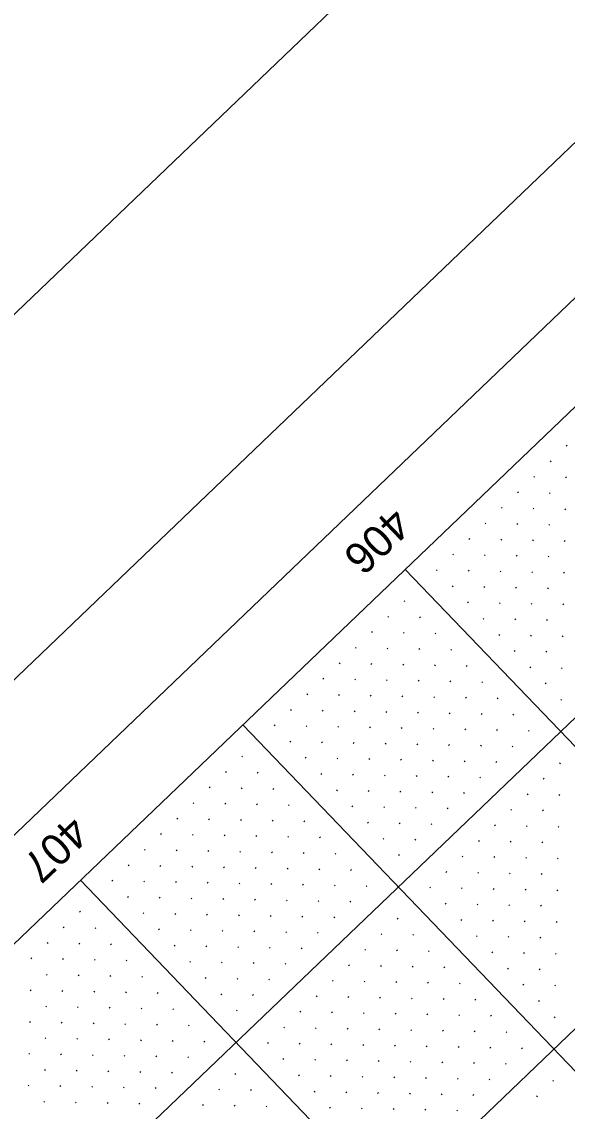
# Model space of a CAD drawing. Extents: x 2148987 to 2151117, y 142806 to 144993.
# Drawn here: x 2150042.8 to 2150164.2, y 144504.6 to 144747.2 of the extents above; entities that cross this region are included whole.
import ezdxf

# ---------------------------------------------------------------- set-up
doc = ezdxf.new("R2010")
doc.units = 0
for name, color, linetype in [('BASELINE', 7, 'Continuous'), ('PR_ABUT_PH3', 7, 'Continuous'), ('PR_PIER_PH3', 7, 'Continuous'), ('PR_Road_Concrete', 7, 'Continuous'), ('SHT_Profile_Grid_Minor', 7, 'Continuous'), ('Wall D Bore Txt', 7, 'Continuous')]:
    doc.layers.add(name, color=color, linetype=linetype)

msp = doc.modelspace()

# ---------------------------------------------------------------- linework, layer by layer
at = {"layer": 'BASELINE'}
msp.add_lwpolyline([(2151029.45, 144024.32), (2149802.07, 142848.08), (2149040.98, 143642.27), (2150268.36, 144818.51)], close=True, dxfattribs=at)
at = {"layer": 'PR_ABUT_PH3'}
msp.add_lwpolyline([(2151117.11, 144051.19), (2149817.52, 142805.76), (2148987.24, 143672.15), (2150286.82, 144917.58)], close=True, dxfattribs=at)
at = {"layer": 'PR_PIER_PH3'}
for p, q in [((2150261.97, 144684.26), (2149124.83, 143594.52)), ((2150296.56, 144648.16), (2149159.43, 143558.42)), ((2150128.1, 144625.23), (2150449.83, 144289.5)), ((2150092, 144590.63), (2150413.73, 144254.91)), ((2150055.9, 144556.04), (2150377.63, 144220.31))]:
    msp.add_line(p, q, dxfattribs=at)
at = {"layer": 'PR_Road_Concrete'}
msp.add_line((2150227.37, 144720.36), (2149279.76, 143812.24), dxfattribs=at)
msp.add_lwpolyline([(2150941.76, 143974.91), (2149804.63, 142885.16), (2149078.13, 143643.25), (2150215.26, 144733)], close=True, dxfattribs=at)
at = {"layer": 'SHT_Profile_Grid_Minor'}
for p, q in [((2150164.14, 144652.84), (2150163.96, 144652.67)), ((2150160.53, 144649.38), (2150160.35, 144649.21)), ((2150156.92, 144645.92), (2150156.74, 144645.75)), ((2150163.99, 144645.77), (2150163.81, 144645.6)), ((2150153.31, 144642.46), (2150153.13, 144642.29)), ((2150160.38, 144642.31), (2150160.2, 144642.14)), ((2150149.7, 144639), (2150149.52, 144638.83)), ((2150156.77, 144638.85), (2150156.59, 144638.68)), ((2150163.84, 144638.7), (2150163.66, 144638.53)), ((2150146.09, 144635.54), (2150145.91, 144635.37)), ((2150153.16, 144635.39), (2150152.98, 144635.22)), ((2150160.23, 144635.24), (2150160.05, 144635.07)), ((2150142.48, 144632.08), (2150142.3, 144631.91)), ((2150149.55, 144631.93), (2150149.37, 144631.76)), ((2150156.62, 144631.78), (2150156.44, 144631.61)), ((2150163.69, 144631.63), (2150163.51, 144631.46)), ((2150138.87, 144628.62), (2150138.69, 144628.45)), ((2150145.94, 144628.47), (2150145.76, 144628.3)), ((2150153.01, 144628.32), (2150152.83, 144628.15)), ((2150160.08, 144628.17), (2150159.9, 144628)), ((2150135.26, 144625.16), (2150135.08, 144624.99)), ((2150142.33, 144625.01), (2150142.15, 144624.84)), ((2150149.4, 144624.86), (2150149.22, 144624.69)), ((2150156.47, 144624.71), (2150156.29, 144624.54)), ((2150163.54, 144624.56), (2150163.36, 144624.39)), ((2150138.72, 144621.55), (2150138.54, 144621.38)), ((2150145.79, 144621.4), (2150145.61, 144621.23)), ((2150152.86, 144621.25), (2150152.68, 144621.08)), ((2150159.93, 144621.1), (2150159.75, 144620.93)), ((2150128.04, 144618.24), (2150127.86, 144618.07)), ((2150142.18, 144617.94), (2150142, 144617.77)), ((2150149.25, 144617.79), (2150149.07, 144617.62)), ((2150156.32, 144617.64), (2150156.14, 144617.47)), ((2150163.39, 144617.49), (2150163.2, 144617.32)), ((2150124.43, 144614.78), (2150124.25, 144614.61)), ((2150131.5, 144614.63), (2150131.32, 144614.46)), ((2150145.64, 144614.33), (2150145.46, 144614.16)), ((2150152.71, 144614.18), (2150152.53, 144614.01)), ((2150159.78, 144614.03), (2150159.59, 144613.86)), ((2150120.82, 144611.33), (2150120.64, 144611.15)), ((2150127.89, 144611.17), (2150127.71, 144611)), ((2150134.96, 144611.02), (2150134.78, 144610.85)), ((2150149.1, 144610.72), (2150148.92, 144610.55)), ((2150156.17, 144610.57), (2150155.99, 144610.4)), ((2150163.23, 144610.42), (2150163.05, 144610.25)), ((2150117.21, 144607.87), (2150117.03, 144607.69)), ((2150124.28, 144607.72), (2150124.1, 144607.54)), ((2150131.35, 144607.56), (2150131.17, 144607.39)), ((2150138.42, 144607.41), (2150138.24, 144607.24)), ((2150152.56, 144607.11), (2150152.38, 144606.94)), ((2150159.63, 144606.96), (2150159.44, 144606.79)), ((2150113.6, 144604.41), (2150113.42, 144604.23)), ((2150120.67, 144604.26), (2150120.49, 144604.08)), ((2150127.74, 144604.11), (2150127.56, 144603.93)), ((2150134.81, 144603.95), (2150134.63, 144603.78)), ((2150141.88, 144603.8), (2150141.7, 144603.63)), ((2150156.02, 144603.5), (2150155.83, 144603.33)), ((2150163.08, 144603.35), (2150162.9, 144603.18)), ((2150109.99, 144600.95), (2150109.81, 144600.77)), ((2150117.06, 144600.8), (2150116.88, 144600.62)), ((2150124.13, 144600.65), (2150123.95, 144600.47)), ((2150131.2, 144600.5), (2150131.02, 144600.32)), ((2150138.27, 144600.34), (2150138.09, 144600.17)), ((2150145.34, 144600.19), (2150145.16, 144600.02)), ((2150159.47, 144599.89), (2150159.29, 144599.72)), ((2150106.38, 144597.49), (2150106.2, 144597.31)), ((2150113.45, 144597.34), (2150113.27, 144597.16)), ((2150120.52, 144597.19), (2150120.34, 144597.01)), ((2150127.59, 144597.04), (2150127.41, 144596.86)), ((2150134.66, 144596.89), (2150134.48, 144596.71)), ((2150141.73, 144596.73), (2150141.55, 144596.56)), ((2150148.8, 144596.58), (2150148.61, 144596.41)), ((2150162.93, 144596.28), (2150162.75, 144596.11)), ((2150102.77, 144594.03), (2150102.59, 144593.85)), ((2150109.84, 144593.88), (2150109.66, 144593.7)), ((2150116.91, 144593.73), (2150116.73, 144593.55)), ((2150123.98, 144593.58), (2150123.8, 144593.4)), ((2150131.05, 144593.43), (2150130.87, 144593.25)), ((2150138.12, 144593.28), (2150137.94, 144593.1)), ((2150145.19, 144593.12), (2150145, 144592.95)), ((2150152.25, 144592.97), (2150152.07, 144592.8)), ((2150099.16, 144590.57), (2150098.98, 144590.39)), ((2150106.23, 144590.42), (2150106.05, 144590.24)), ((2150113.3, 144590.27), (2150113.12, 144590.09)), ((2150120.37, 144590.12), (2150120.19, 144589.94)), ((2150127.44, 144589.97), (2150127.26, 144589.79)), ((2150134.51, 144589.82), (2150134.33, 144589.64)), ((2150141.58, 144589.67), (2150141.39, 144589.49)), ((2150148.64, 144589.51), (2150148.46, 144589.34)), ((2150155.71, 144589.36), (2150155.53, 144589.19)), ((2150102.62, 144586.96), (2150102.44, 144586.79)), ((2150109.69, 144586.81), (2150109.51, 144586.63)), ((2150116.76, 144586.66), (2150116.58, 144586.48)), ((2150123.83, 144586.51), (2150123.65, 144586.33)), ((2150130.9, 144586.36), (2150130.72, 144586.18)), ((2150137.97, 144586.21), (2150137.78, 144586.03)), ((2150145.03, 144586.06), (2150144.85, 144585.88)), ((2150152.1, 144585.9), (2150151.92, 144585.73)), ((2150091.94, 144583.65), (2150091.76, 144583.48)), ((2150106.08, 144583.35), (2150105.9, 144583.18)), ((2150113.15, 144583.2), (2150112.97, 144583.02)), ((2150120.22, 144583.05), (2150120.04, 144582.87)), ((2150127.29, 144582.9), (2150127.11, 144582.72)), ((2150134.36, 144582.75), (2150134.17, 144582.57)), ((2150141.42, 144582.6), (2150141.24, 144582.42)), ((2150148.49, 144582.45), (2150148.31, 144582.27)), ((2150088.33, 144580.19), (2150088.15, 144580.02)), ((2150095.4, 144580.04), (2150095.22, 144579.87)), ((2150162.63, 144582.14), (2150162.45, 144581.97)), ((2150109.54, 144579.74), (2150109.36, 144579.57)), ((2150116.61, 144579.59), (2150116.43, 144579.41)), ((2150123.68, 144579.44), (2150123.5, 144579.26)), ((2150130.75, 144579.29), (2150130.56, 144579.11)), ((2150137.81, 144579.14), (2150137.63, 144578.96)), ((2150144.88, 144578.99), (2150144.7, 144578.81)), ((2150159.02, 144578.69), (2150158.84, 144578.51)), ((2150084.72, 144576.73), (2150084.54, 144576.56)), ((2150091.79, 144576.58), (2150091.61, 144576.41)), ((2150098.86, 144576.43), (2150098.68, 144576.26)), ((2150113, 144576.13), (2150112.82, 144575.96)), ((2150120.07, 144575.98), (2150119.89, 144575.8)), ((2150127.14, 144575.83), (2150126.95, 144575.65)), ((2150134.2, 144575.68), (2150134.02, 144575.5)), ((2150141.27, 144575.53), (2150141.09, 144575.35)), ((2150155.41, 144575.23), (2150155.23, 144575.05)), ((2150081.11, 144573.27), (2150080.93, 144573.1)), ((2150088.18, 144573.12), (2150088, 144572.95)), ((2150095.25, 144572.97), (2150095.07, 144572.8)), ((2150102.32, 144572.82), (2150102.14, 144572.65)), ((2150162.48, 144575.08), (2150162.3, 144574.9)), ((2150116.46, 144572.52), (2150116.28, 144572.35)), ((2150123.53, 144572.37), (2150123.35, 144572.19)), ((2150130.59, 144572.22), (2150130.41, 144572.04)), ((2150137.66, 144572.07), (2150137.48, 144571.89)), ((2150151.8, 144571.77), (2150151.62, 144571.59)), ((2150158.87, 144571.62), (2150158.69, 144571.44)), ((2150077.5, 144569.81), (2150077.32, 144569.64)), ((2150084.57, 144569.66), (2150084.39, 144569.49)), ((2150091.64, 144569.51), (2150091.46, 144569.34)), ((2150098.71, 144569.36), (2150098.53, 144569.19)), ((2150105.78, 144569.21), (2150105.6, 144569.04)), ((2150119.92, 144568.91), (2150119.74, 144568.74)), ((2150126.99, 144568.76), (2150126.8, 144568.58)), ((2150134.05, 144568.61), (2150133.87, 144568.43)), ((2150148.19, 144568.31), (2150148.01, 144568.13)), ((2150155.26, 144568.16), (2150155.08, 144567.98)), ((2150162.33, 144568.01), (2150162.15, 144567.83)), ((2150073.89, 144566.35), (2150073.71, 144566.18)), ((2150080.96, 144566.2), (2150080.78, 144566.03)), ((2150088.03, 144566.05), (2150087.85, 144565.88)), ((2150095.1, 144565.9), (2150094.92, 144565.73)), ((2150102.17, 144565.75), (2150101.99, 144565.58)), ((2150109.24, 144565.6), (2150109.06, 144565.43)), ((2150123.38, 144565.3), (2150123.19, 144565.13)), ((2150130.44, 144565.15), (2150130.26, 144564.97)), ((2150144.58, 144564.85), (2150144.4, 144564.67)), ((2150151.65, 144564.7), (2150151.47, 144564.52)), ((2150158.72, 144564.55), (2150158.54, 144564.37)), ((2150070.28, 144562.89), (2150070.1, 144562.72)), ((2150077.35, 144562.74), (2150077.17, 144562.57)), ((2150084.42, 144562.59), (2150084.24, 144562.42)), ((2150091.49, 144562.44), (2150091.31, 144562.27)), ((2150098.56, 144562.29), (2150098.38, 144562.12)), ((2150105.63, 144562.14), (2150105.45, 144561.97)), ((2150112.7, 144561.99), (2150112.52, 144561.82)), ((2150126.83, 144561.69), (2150126.65, 144561.52)), ((2150140.97, 144561.39), (2150140.79, 144561.21)), ((2150148.04, 144561.24), (2150147.86, 144561.06)), ((2150155.11, 144561.09), (2150154.93, 144560.91)), ((2150162.18, 144560.94), (2150162, 144560.76)), ((2150066.67, 144559.43), (2150066.49, 144559.26)), ((2150073.74, 144559.28), (2150073.56, 144559.11)), ((2150080.81, 144559.13), (2150080.63, 144558.96)), ((2150087.88, 144558.98), (2150087.7, 144558.81)), ((2150094.95, 144558.83), (2150094.77, 144558.66)), ((2150102.02, 144558.68), (2150101.84, 144558.51)), ((2150109.09, 144558.53), (2150108.91, 144558.36)), ((2150116.16, 144558.38), (2150115.97, 144558.21)), ((2150063.06, 144555.97), (2150062.88, 144555.8)), ((2150070.13, 144555.82), (2150069.95, 144555.65)), ((2150137.36, 144557.93), (2150137.18, 144557.75)), ((2150144.43, 144557.78), (2150144.25, 144557.6)), ((2150151.5, 144557.63), (2150151.32, 144557.45)), ((2150158.57, 144557.48), (2150158.39, 144557.3)), ((2150077.2, 144555.67), (2150077.02, 144555.5)), ((2150084.27, 144555.52), (2150084.09, 144555.35)), ((2150091.34, 144555.37), (2150091.16, 144555.2)), ((2150098.41, 144555.22), (2150098.23, 144555.05)), ((2150105.48, 144555.07), (2150105.3, 144554.9)), ((2150112.55, 144554.92), (2150112.36, 144554.75)), ((2150119.61, 144554.77), (2150119.43, 144554.6)), ((2150133.75, 144554.47), (2150133.57, 144554.3)), ((2150140.82, 144554.32), (2150140.64, 144554.15)), ((2150147.89, 144554.17), (2150147.71, 144553.99)), ((2150154.96, 144554.02), (2150154.78, 144553.84)), ((2150162.03, 144553.87), (2150161.85, 144553.69)), ((2150066.52, 144552.36), (2150066.34, 144552.19)), ((2150073.59, 144552.21), (2150073.41, 144552.04)), ((2150080.66, 144552.06), (2150080.48, 144551.89)), ((2150087.73, 144551.91), (2150087.55, 144551.74)), ((2150094.8, 144551.76), (2150094.62, 144551.59)), ((2150101.87, 144551.61), (2150101.69, 144551.44)), ((2150108.94, 144551.46), (2150108.75, 144551.29)), ((2150116, 144551.31), (2150115.82, 144551.14)), ((2150137.21, 144550.86), (2150137.03, 144550.69)), ((2150055.84, 144549.05), (2150055.66, 144548.88)), ((2150069.98, 144548.75), (2150069.8, 144548.58)), ((2150077.05, 144548.6), (2150076.87, 144548.43)), ((2150084.12, 144548.45), (2150083.94, 144548.28)), ((2150144.28, 144550.71), (2150144.1, 144550.54)), ((2150151.35, 144550.56), (2150151.17, 144550.38)), ((2150158.42, 144550.41), (2150158.24, 144550.23)), ((2150091.19, 144548.3), (2150091.01, 144548.13)), ((2150098.26, 144548.15), (2150098.08, 144547.98)), ((2150105.33, 144548), (2150105.14, 144547.83)), ((2150112.39, 144547.85), (2150112.21, 144547.68)), ((2150126.53, 144547.55), (2150126.35, 144547.38)), ((2150140.67, 144547.25), (2150140.49, 144547.08)), ((2150147.74, 144547.1), (2150147.56, 144546.93)), ((2150154.81, 144546.95), (2150154.63, 144546.77)), ((2150161.88, 144546.8), (2150161.7, 144546.62)), ((2150052.23, 144545.59), (2150052.05, 144545.42)), ((2150059.3, 144545.44), (2150059.12, 144545.27)), ((2150073.44, 144545.14), (2150073.26, 144544.97)), ((2150080.51, 144544.99), (2150080.33, 144544.82)), ((2150087.58, 144544.84), (2150087.4, 144544.67)), ((2150094.65, 144544.69), (2150094.47, 144544.52)), ((2150101.72, 144544.54), (2150101.53, 144544.37)), ((2150108.78, 144544.39), (2150108.6, 144544.22)), ((2150122.92, 144544.09), (2150122.74, 144543.92)), ((2150129.99, 144543.94), (2150129.81, 144543.77)), ((2150144.13, 144543.64), (2150143.95, 144543.47)), ((2150048.62, 144542.13), (2150048.44, 144541.96)), ((2150055.69, 144541.98), (2150055.51, 144541.81)), ((2150062.76, 144541.83), (2150062.58, 144541.66)), ((2150076.9, 144541.53), (2150076.72, 144541.36)), ((2150083.97, 144541.38), (2150083.79, 144541.21)), ((2150091.04, 144541.23), (2150090.86, 144541.06)), ((2150151.2, 144543.49), (2150151.02, 144543.32)), ((2150158.27, 144543.34), (2150158.09, 144543.16)), ((2150098.11, 144541.08), (2150097.92, 144540.91)), ((2150105.17, 144540.93), (2150104.99, 144540.76)), ((2150119.31, 144540.63), (2150119.13, 144540.46)), ((2150126.38, 144540.48), (2150126.2, 144540.31)), ((2150133.45, 144540.33), (2150133.27, 144540.16)), ((2150147.59, 144540.03), (2150147.41, 144539.86)), ((2150154.66, 144539.88), (2150154.48, 144539.71)), ((2150161.73, 144539.73), (2150161.55, 144539.55)), ((2150045.01, 144538.68), (2150044.83, 144538.5)), ((2150052.08, 144538.52), (2150051.9, 144538.35)), ((2150059.15, 144538.37), (2150058.97, 144538.2)), ((2150066.22, 144538.22), (2150066.04, 144538.05)), ((2150080.36, 144537.92), (2150080.18, 144537.75)), ((2150087.43, 144537.77), (2150087.25, 144537.6)), ((2150094.5, 144537.62), (2150094.31, 144537.45)), ((2150101.56, 144537.47), (2150101.38, 144537.3)), ((2150115.7, 144537.17), (2150115.52, 144537)), ((2150122.77, 144537.02), (2150122.59, 144536.85)), ((2150129.84, 144536.87), (2150129.66, 144536.7)), ((2150136.91, 144536.72), (2150136.73, 144536.55)), ((2150151.05, 144536.42), (2150150.87, 144536.25)), ((2150048.47, 144535.07), (2150048.29, 144534.89)), ((2150055.54, 144534.91), (2150055.36, 144534.74)), ((2150062.61, 144534.76), (2150062.43, 144534.59)), ((2150069.68, 144534.61), (2150069.5, 144534.44)), ((2150083.82, 144534.31), (2150083.64, 144534.14)), ((2150090.89, 144534.16), (2150090.7, 144533.99)), ((2150097.95, 144534.01), (2150097.77, 144533.84)), ((2150158.12, 144536.27), (2150157.94, 144536.1)), ((2150044.86, 144531.61), (2150044.68, 144531.43)), ((2150051.93, 144531.46), (2150051.75, 144531.28)), ((2150112.09, 144533.71), (2150111.91, 144533.54)), ((2150119.16, 144533.56), (2150118.98, 144533.39)), ((2150126.23, 144533.41), (2150126.05, 144533.24)), ((2150133.3, 144533.26), (2150133.12, 144533.09)), ((2150140.37, 144533.11), (2150140.19, 144532.94)), ((2150154.51, 144532.81), (2150154.33, 144532.64)), ((2150161.58, 144532.66), (2150161.4, 144532.49)), ((2150059, 144531.3), (2150058.82, 144531.13)), ((2150066.07, 144531.15), (2150065.89, 144530.98)), ((2150073.14, 144531), (2150072.96, 144530.83)), ((2150087.28, 144530.7), (2150087.1, 144530.53)), ((2150094.35, 144530.55), (2150094.16, 144530.38)), ((2150108.48, 144530.25), (2150108.3, 144530.08)), ((2150115.55, 144530.1), (2150115.37, 144529.93)), ((2150122.62, 144529.95), (2150122.44, 144529.78)), ((2150129.69, 144529.8), (2150129.51, 144529.63)), ((2150136.76, 144529.65), (2150136.58, 144529.48)), ((2150143.83, 144529.5), (2150143.65, 144529.33)), ((2150157.97, 144529.2), (2150157.79, 144529.03)), ((2150048.32, 144528), (2150048.14, 144527.82)), ((2150055.39, 144527.85), (2150055.21, 144527.67)), ((2150062.46, 144527.69), (2150062.28, 144527.52)), ((2150069.53, 144527.54), (2150069.35, 144527.37)), ((2150076.6, 144527.39), (2150076.42, 144527.22)), ((2150090.74, 144527.09), (2150090.55, 144526.92)), ((2150104.87, 144526.79), (2150104.69, 144526.62)), ((2150111.94, 144526.64), (2150111.76, 144526.47)), ((2150044.71, 144524.54), (2150044.53, 144524.36)), ((2150051.78, 144524.39), (2150051.6, 144524.21)), ((2150058.85, 144524.24), (2150058.67, 144524.06)), ((2150119.01, 144526.49), (2150118.83, 144526.32)), ((2150126.08, 144526.34), (2150125.9, 144526.17)), ((2150133.15, 144526.19), (2150132.97, 144526.02)), ((2150140.22, 144526.04), (2150140.04, 144525.87)), ((2150147.29, 144525.89), (2150147.11, 144525.72)), ((2150161.43, 144525.59), (2150161.25, 144525.42)), ((2150065.92, 144524.08), (2150065.74, 144523.91)), ((2150072.99, 144523.93), (2150072.81, 144523.76)), ((2150080.06, 144523.78), (2150079.88, 144523.61)), ((2150101.26, 144523.33), (2150101.08, 144523.16)), ((2150108.33, 144523.18), (2150108.15, 144523.01)), ((2150115.4, 144523.03), (2150115.22, 144522.86)), ((2150122.47, 144522.88), (2150122.29, 144522.71)), ((2150129.54, 144522.73), (2150129.36, 144522.56)), ((2150136.61, 144522.58), (2150136.43, 144522.41)), ((2150143.68, 144522.43), (2150143.5, 144522.26)), ((2150150.75, 144522.28), (2150150.57, 144522.11)), ((2150048.17, 144520.93), (2150047.99, 144520.75)), ((2150055.24, 144520.78), (2150055.06, 144520.6)), ((2150062.31, 144520.63), (2150062.13, 144520.45)), ((2150069.38, 144520.48), (2150069.2, 144520.3)), ((2150076.45, 144520.32), (2150076.27, 144520.15)), ((2150083.52, 144520.17), (2150083.33, 144520)), ((2150097.65, 144519.87), (2150097.47, 144519.7)), ((2150104.72, 144519.72), (2150104.54, 144519.55)), ((2150111.79, 144519.57), (2150111.61, 144519.4)), ((2150118.86, 144519.42), (2150118.68, 144519.25)), ((2150044.56, 144517.47), (2150044.38, 144517.29)), ((2150051.63, 144517.32), (2150051.45, 144517.14)), ((2150058.7, 144517.17), (2150058.52, 144516.99)), ((2150065.77, 144517.02), (2150065.59, 144516.84)), ((2150125.93, 144519.27), (2150125.75, 144519.1)), ((2150133, 144519.12), (2150132.82, 144518.95)), ((2150140.07, 144518.97), (2150139.89, 144518.8)), ((2150147.14, 144518.82), (2150146.96, 144518.65)), ((2150154.21, 144518.67), (2150154.03, 144518.5)), ((2150072.84, 144516.87), (2150072.66, 144516.69)), ((2150079.91, 144516.71), (2150079.72, 144516.54)), ((2150101.11, 144516.26), (2150100.93, 144516.09)), ((2150108.18, 144516.11), (2150108, 144515.94)), ((2150115.25, 144515.96), (2150115.07, 144515.79)), ((2150122.32, 144515.81), (2150122.14, 144515.64)), ((2150129.39, 144515.66), (2150129.21, 144515.49)), ((2150136.46, 144515.51), (2150136.28, 144515.34)), ((2150143.53, 144515.36), (2150143.35, 144515.19)), ((2150150.6, 144515.21), (2150150.42, 144515.04)), ((2150048.02, 144513.86), (2150047.84, 144513.68)), ((2150055.09, 144513.71), (2150054.91, 144513.53)), ((2150062.16, 144513.56), (2150061.98, 144513.38)), ((2150069.23, 144513.41), (2150069.05, 144513.23)), ((2150076.3, 144513.26), (2150076.11, 144513.08)), ((2150090.43, 144512.95), (2150090.25, 144512.78)), ((2150104.57, 144512.65), (2150104.39, 144512.48)), ((2150111.64, 144512.5), (2150111.46, 144512.33)), ((2150118.71, 144512.35), (2150118.53, 144512.18)), ((2150125.78, 144512.2), (2150125.6, 144512.03)), ((2150132.85, 144512.05), (2150132.67, 144511.88)), ((2150044.41, 144510.4), (2150044.23, 144510.22)), ((2150051.48, 144510.25), (2150051.3, 144510.07)), ((2150058.55, 144510.1), (2150058.37, 144509.92)), ((2150065.62, 144509.95), (2150065.44, 144509.77)), ((2150072.69, 144509.8), (2150072.5, 144509.62)), ((2150139.92, 144511.9), (2150139.74, 144511.73)), ((2150146.99, 144511.75), (2150146.81, 144511.58)), ((2150161.13, 144511.45), (2150160.95, 144511.28)), ((2150086.82, 144509.49), (2150086.64, 144509.32)), ((2150093.89, 144509.34), (2150093.71, 144509.17)), ((2150108.03, 144509.04), (2150107.85, 144508.87)), ((2150115.1, 144508.89), (2150114.92, 144508.72)), ((2150122.17, 144508.74), (2150121.99, 144508.57)), ((2150129.24, 144508.59), (2150129.06, 144508.42)), ((2150136.31, 144508.44), (2150136.13, 144508.27)), ((2150143.38, 144508.29), (2150143.2, 144508.12)), ((2150157.52, 144507.99), (2150157.34, 144507.82)), ((2150047.87, 144506.79), (2150047.69, 144506.61)), ((2150054.94, 144506.64), (2150054.76, 144506.46)), ((2150062.01, 144506.49), (2150061.83, 144506.31)), ((2150069.08, 144506.34), (2150068.89, 144506.16)), ((2150083.21, 144506.04), (2150083.03, 144505.86)), ((2150090.28, 144505.88), (2150090.1, 144505.71)), ((2150097.35, 144505.73), (2150097.17, 144505.56)), ((2150111.49, 144505.43), (2150111.31, 144505.26)), ((2150118.56, 144505.28), (2150118.38, 144505.11)), ((2150125.63, 144505.13), (2150125.45, 144504.96)), ((2150132.7, 144504.98), (2150132.52, 144504.81)), ((2150139.77, 144504.83), (2150139.59, 144504.66))]:
    msp.add_line(p, q, dxfattribs=at)

# ---------------------------------------------------------------- texts
at = {"layer": 'Wall D Bore Txt'}
for s, p in [('406', (2150125.23, 144639.45)), ('407', (2150053.62, 144570.82))]:
    msp.add_text(s, height=7, rotation=223.7809, dxfattribs=at).set_placement(p)

doc.saveas('drawing.dxf')
